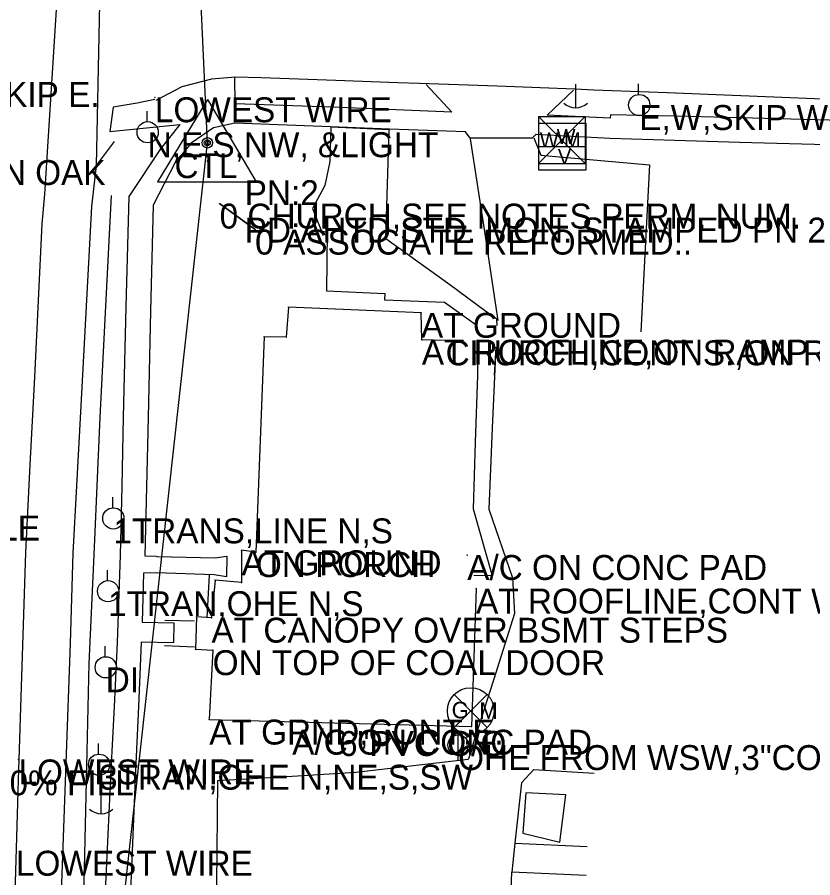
# Model space of a CAD drawing. Extents: x 997398 to 1003416, y 334596 to 337085.
# Drawn here: x 999233.9 to 999393.6, y 335108.7 to 335281.4 of the extents above; entities that cross this region are included whole.
import ezdxf

# ---------------------------------------------------------------- set-up
doc = ezdxf.new("R2010")
doc.units = 0
for name, color, linetype in [('Default', 7, 'Continuous'), ('S_BUILDING', 7, 'Continuous'), ('S_BUILDING_ANNOT', 7, 'Continuous'), ('S_CURB', 7, 'Continuous'), ('S_DITCHLINE', 7, 'Continuous'), ('S_EDGE_CONCRETE', 7, 'Continuous'), ('S_EDGE_PAVEMENT', 7, 'Continuous'), ('S_ELECTRIC_UTILITIES_ANNOT', 7, 'Continuous'), ('S_GAS_UTILITIES', 7, 'Continuous'), ('S_GRD_PT_SYM', 7, 'Continuous'), ('S_MISC_STRUCTURES_ANNOT', 7, 'Continuous'), ('S_MSC_PT_SYM', 7, 'Continuous'), ('S_PAVEMENT_CROWN', 7, 'Continuous'), ('S_PRIMARY_CTL', 7, 'Continuous'), ('S_PRIMARY_CTL_ANNOT', 7, 'Continuous'), ('S_SIDE_DRAIN_ANNOT', 7, 'Continuous'), ('S_SIDEWALK', 7, 'Continuous'), ('S_SIGN', 7, 'Continuous'), ('S_SIGN_ANNOT', 7, 'Continuous'), ('S_STR_PT_SYM', 7, 'Continuous'), ('S_TREE_ANNOT', 7, 'Continuous'), ('S_UTILITY_POLE', 7, 'Continuous'), ('S_UTILITY_POLE_ANNOT', 7, 'Continuous'), ('S_UTL_PT_SYM', 7, 'Continuous'), ('S_WALL', 7, 'Continuous'), ('S_WATER_UTILITIES', 7, 'Continuous')]:
    doc.layers.add(name, color=color, linetype=linetype)

msp = doc.modelspace()

# ---------------------------------------------------------------- linework, layer by layer
at = {"layer": 'Default'}
for p, q in [((999272.07, 335256.17), (999254.77, 335651.12)), ((999206.9, 334665.47), (999272.07, 335256.17))]:
    msp.add_line(p, q, dxfattribs=at)
at = {"layer": 'S_BUILDING'}
for p, q in [((999288.38, 335223.2), (999287.92, 335217.21)), ((999314.96, 335222.06), (999288.38, 335223.2)), ((999315.12, 335216.67), (999314.96, 335222.06)), ((999283.48, 335217.28), (999281.81, 335174.06)), ((999287.92, 335217.21), (999283.48, 335217.28)), ((999319.89, 335216.53), (999315.12, 335216.67)), ((999278.95, 335174.42), (999278.92, 335167.97)), ((999281.81, 335174.06), (999278.95, 335174.42)), ((999273.61, 335168.44), (999272.91, 335160.9)), ((999278.92, 335167.97), (999273.61, 335168.44)), ((999326.01, 335166.74), (999325.1, 335139.1)), ((999269.89, 335161.05), (999269.66, 335154.56)), ((999272.91, 335160.9), (999269.89, 335161.05)), ((999269.66, 335154.56), (999273.14, 335154.38)), ((999273.14, 335154.38), (999272.46, 335140.46)), ((999272.46, 335140.46), (999325.1, 335139.1))]:
    msp.add_line(p, q, dxfattribs=at)
at = {"layer": 'S_CURB'}
msp.add_lwpolyline([(999479.94, 335261.63), (999466.28, 335262.15), (999452.62, 335262.68), (999438.96, 335263.21), (999425.29, 335263.73), (999402.2, 335264.66), (999379.11, 335265.58), (999364.38, 335266.17), (999349.65, 335266.76), (999345.81, 335266.95), (999330.22, 335267.52), (999314.63, 335268.09), (999310.32, 335268.23), (999297.87, 335268.66), (999282.9, 335269.18), (999277.69, 335269.31), (999272.89, 335268.92), (999266.95, 335267.42), (999261.74, 335264.66)], dxfattribs=at)
at = {"layer": 'S_DITCHLINE'}
msp.add_lwpolyline([(999252.77, 335245.59), (999251.64, 335223.38), (999250.51, 335201.16), (999249.91, 335187.35), (999249.3, 335173.53), (999248.31, 335151.72), (999247.75, 335128.15), (999247.19, 335104.58), (999246.61, 335082.45), (999246.03, 335060.31), (999245.59, 335042.2), (999245.16, 335024.09)], dxfattribs=at)
at = {"layer": 'S_EDGE_CONCRETE'}
for points in [[(999330.26, 335219.49), (999330.2, 335220.82), (999327.72, 335222.53), (999320.73, 335227.65), (999307.89, 335236.94), (999308.58, 335258.8), (999296.86, 335259.33), (999296.65, 335252.42), (999295.64, 335247.63), (999293.16, 335243.01), (999294.95, 335238.44), (999296.11, 335238.34), (999295.96, 335226.51), (999307.69, 335225.96), (999307.63, 335224.64), (999319.66, 335224.2), (999326.05, 335219.68)], [(999272.05, 335160.9), (999272.52, 335169.46)], [(999343.99, 335125.34), (999335.96, 335125.79), (999335.36, 335117.66), (999342.79, 335115.87)], [(999342.79, 335115.87), (999343.99, 335125.34)]]:
    msp.add_lwpolyline(points, dxfattribs=at)
at = {"layer": 'S_EDGE_PAVEMENT'}
for points in [[(999250.53, 335290.61), (999250.16, 335271.12), (999249.78, 335251.63)], [(999253.37, 335256.43), (999249.78, 335251.63), (999248.81, 335243.39), (999247.69, 335222.16), (999246.57, 335200.94), (999245.83, 335187.38), (999245.09, 335173.83), (999244.51, 335155.82), (999243.66, 335131.7), (999242.8, 335107.59), (999242.11, 335084.06), (999241.43, 335060.53), (999241.09, 335044.29), (999240.74, 335028.05)], [(999330.41, 335220.52), (999327.66, 335238.75), (999324.91, 335256.98)], [(999337.56, 335257.14), (999339, 335253.7), (999360.79, 335251.76), (999359.92, 335235.01), (999359.06, 335218.27)], [(999325.44, 335135.07), (999324.44, 335132.45), (999301.88, 335129.85), (999288.01, 335129.01), (999274.14, 335128.17), (999273.91, 335107.32), (999273.67, 335086.47), (999273.64, 335073.11), (999273.61, 335059.74), (999273.58, 335046.38), (999273.55, 335033.02), (999273.11, 335010.86)], [(999335.09, 335127.78), (999337.61, 335130.43), (999349.71, 335129.72)], [(999335.09, 335127.78), (999333.79, 335115.69)], [(999331.73, 335071.66), (999332.45, 335090.76), (999333.17, 335109.85)]]:
    msp.add_lwpolyline(points, dxfattribs=at)
at = {"layer": 'S_GAS_UTILITIES'}
for p, q in [((999321.61, 335138.87), (999328.23, 335145.49)), ((999321.61, 335145.49), (999328.23, 335138.87))]:
    msp.add_line(p, q, dxfattribs=at)
msp.add_circle((999324.92, 335142.18), 4.68, dxfattribs=at)
at = {"layer": 'S_GRD_PT_SYM'}
for points in [[(999261.55, 335265.3), (999261.55, 335265.35), (999261.55, 335265.3), (999261.5, 335265.3), (999261.55, 335265.3), (999261.55, 335265.25), (999261.55, 335265.3), (999261.6, 335265.3)], [(999234.16, 335132.46), (999234.16, 335132.51), (999234.16, 335132.46), (999234.11, 335132.46), (999234.16, 335132.46), (999234.16, 335132.41), (999234.16, 335132.46), (999234.21, 335132.46)]]:
    msp.add_lwpolyline(points, dxfattribs=at)
at = {"layer": 'S_MSC_PT_SYM'}
for points in [[(999274.54, 335243.97), (999274.54, 335244.02), (999274.54, 335243.97), (999274.49, 335243.97), (999274.54, 335243.97), (999274.54, 335243.92), (999274.54, 335243.97), (999274.59, 335243.97)], [(999281.65, 335238.75), (999281.65, 335238.8), (999281.65, 335238.75), (999281.6, 335238.75), (999281.65, 335238.75), (999281.65, 335238.7), (999281.65, 335238.75), (999281.7, 335238.75)], [(999281.7, 335238.75), (999281.7, 335238.8), (999281.7, 335238.75), (999281.65, 335238.75), (999281.7, 335238.75), (999281.7, 335238.7), (999281.7, 335238.75), (999281.75, 335238.75)], [(999324.23, 335173.48), (999324.23, 335173.53), (999324.23, 335173.48), (999324.18, 335173.48), (999324.23, 335173.48), (999324.23, 335173.43), (999324.23, 335173.48), (999324.28, 335173.48)], [(999289.1, 335138.43), (999289.1, 335138.48), (999289.1, 335138.43), (999289.05, 335138.43), (999289.1, 335138.43), (999289.1, 335138.38), (999289.1, 335138.43), (999289.15, 335138.43)], [(999298.5, 335138.16), (999298.5, 335138.21), (999298.5, 335138.16), (999298.45, 335138.16), (999298.5, 335138.16), (999298.5, 335138.11), (999298.5, 335138.16), (999298.55, 335138.16)]]:
    msp.add_lwpolyline(points, dxfattribs=at)
at = {"layer": 'S_PAVEMENT_CROWN'}
msp.add_lwpolyline([(999231.13, 335025.58), (999231.54, 335039.84), (999231.96, 335054.1), (999232.37, 335068.37), (999232.78, 335082.63), (999233.49, 335105.48), (999234.2, 335128.32), (999234.91, 335151.16), (999235.62, 335174.01), (999236.52, 335191.6), (999237.42, 335209.19), (999238.19, 335224.55), (999238.95, 335239.91), (999239.44, 335245.85), (999240.93, 335269.15), (999242.42, 335292.45)], dxfattribs=at)
at = {"layer": 'S_PRIMARY_CTL'}
for p, q in [((999272.07, 335264.87), (999262.04, 335248.36)), ((999272.07, 335264.87), (999281.89, 335248.36)), ((999262.04, 335248.36), (999281.89, 335248.36))]:
    msp.add_line(p, q, dxfattribs=at)
for radius in [1.04, 0.609, 0.344]:
    msp.add_circle((999272.07, 335256.17), radius, dxfattribs=at)
at = {"layer": 'S_SIDEWALK'}
for points in [[(999316, 335267.89), (999321.17, 335262.33), (999296.97, 335263.29), (999277.65, 335264.02), (999277.6, 335269.25)], [(999479.54, 335257.17), (999465.91, 335257.86), (999452.28, 335258.55), (999438.64, 335259.23), (999425.01, 335259.92), (999401.97, 335260.55), (999378.93, 335261.19), (999365.95, 335261.49), (999352.97, 335261.78), (999352.89, 335261.13), (999340.29, 335261.71), (999345.53, 335266.72)], [(999261.5, 335264.87), (999257.97, 335264.12), (999253.16, 335263.29), (999252.5, 335258.44), (999266.54, 335259.86), (999262.66, 335254.95), (999256.3, 335245.42)], [(999479.13, 335252.32), (999465.35, 335252.98), (999451.57, 335253.65), (999437.79, 335254.31), (999424.01, 335254.97), (999401.43, 335255.6), (999378.85, 335256.22), (999365.86, 335256.64), (999352.87, 335257.07), (999338.02, 335257.84), (999337.27, 335257.09), (999324.82, 335257.13), (999323.89, 335258.38), (999308.61, 335258.94), (999296.79, 335259.38), (999277.61, 335260.14), (999273.31, 335259.2), (999268.8, 335256.09), (999265.61, 335252.19), (999261.19, 335243.68)], [(999256.3, 335245.42), (999255.74, 335223.28), (999255.18, 335201.13)], [(999261.19, 335243.68), (999260.69, 335222.38), (999260.19, 335201.09)], [(999326.27, 335215.31), (999326.26, 335209.47)], [(999329.98, 335215.17), (999329.26, 335198.93), (999328.54, 335182.7)], [(999329.98, 335215.17), (999329.6, 335209.59)], [(999326.26, 335209.47), (999325.85, 335196.11), (999325.43, 335182.76)], [(999255.18, 335201.13), (999254.88, 335187.29), (999254.58, 335173.44), (999253.96, 335155.96), (999253.34, 335143.12), (999252.73, 335130.28), (999252.11, 335117.44), (999251.5, 335104.6), (999250.76, 335082.39), (999250.02, 335060.17), (999249.36, 335042.19), (999248.7, 335024.21)], [(999260.19, 335201.09), (999259.85, 335187.19), (999259.51, 335173.29), (999261.77, 335173.24), (999261.91, 335173.2), (999273.63, 335172.94), (999275.99, 335173.22), (999275.89, 335169.08), (999273.44, 335169.51), (999261.84, 335169.89), (999259.26, 335169.84), (999258.98, 335159.99), (999265.32, 335159.89), (999265.3, 335155.88), (999258.79, 335155.99), (999258.23, 335143.09), (999257.67, 335130.2), (999257.11, 335117.3), (999256.56, 335104.4), (999255.74, 335082.14), (999254.93, 335059.88), (999254.31, 335042.1), (999253.7, 335024.32)], [(999328.54, 335182.7), (999333.29, 335168.87), (999333.74, 335161.76), (999329.47, 335148.4), (999325.21, 335135.04)], [(999325.43, 335182.76), (999329.21, 335169.3), (999325.52, 335169.38)], [(999333.79, 335115.69), (999333.17, 335109.85)], [(999333.79, 335115.69), (999348.33, 335115.02)], [(999348.1, 335109.19), (999333.17, 335109.85)]]:
    msp.add_lwpolyline(points, dxfattribs=at)
at = {"layer": 'S_SIGN'}
for p, q in [((999281.7, 335238.75), (999274.54, 335243.97)), ((999274.54, 335243.97), (999281.65, 335238.75))]:
    msp.add_line(p, q, dxfattribs=at)
at = {"layer": 'S_STR_PT_SYM'}
for points in [[(999288.38, 335223.2), (999288.38, 335223.25), (999288.38, 335223.2), (999288.33, 335223.2), (999288.38, 335223.2), (999288.38, 335223.15), (999288.38, 335223.2), (999288.43, 335223.2)], [(999314.96, 335222.06), (999314.96, 335222.11), (999314.96, 335222.06), (999314.91, 335222.06), (999314.96, 335222.06), (999314.96, 335222.01), (999314.96, 335222.06), (999315.01, 335222.06)], [(999283.48, 335217.28), (999283.48, 335217.33), (999283.48, 335217.28), (999283.43, 335217.28), (999283.48, 335217.28), (999283.48, 335217.23), (999283.48, 335217.28), (999283.53, 335217.28)], [(999287.92, 335217.21), (999287.92, 335217.26), (999287.92, 335217.21), (999287.87, 335217.21), (999287.92, 335217.21), (999287.92, 335217.16), (999287.92, 335217.21), (999287.97, 335217.21)], [(999315.12, 335216.67), (999315.12, 335216.72), (999315.12, 335216.67), (999315.07, 335216.67), (999315.12, 335216.67), (999315.12, 335216.62), (999315.12, 335216.67), (999315.17, 335216.67)], [(999319.89, 335216.53), (999319.89, 335216.58), (999319.89, 335216.53), (999319.84, 335216.53), (999319.89, 335216.53), (999319.89, 335216.48), (999319.89, 335216.53), (999319.94, 335216.53)], [(999278.95, 335174.42), (999278.95, 335174.47), (999278.95, 335174.42), (999278.9, 335174.42), (999278.95, 335174.42), (999278.95, 335174.37), (999278.95, 335174.42), (999279, 335174.42)], [(999281.81, 335174.06), (999281.81, 335174.11), (999281.81, 335174.06), (999281.76, 335174.06), (999281.81, 335174.06), (999281.81, 335174.01), (999281.81, 335174.06), (999281.86, 335174.06)], [(999273.61, 335168.44), (999273.61, 335168.49), (999273.61, 335168.44), (999273.56, 335168.44), (999273.61, 335168.44), (999273.61, 335168.39), (999273.61, 335168.44), (999273.66, 335168.44)], [(999278.92, 335167.97), (999278.92, 335168.02), (999278.92, 335167.97), (999278.87, 335167.97), (999278.92, 335167.97), (999278.92, 335167.92), (999278.92, 335167.97), (999278.97, 335167.97)], [(999326.01, 335166.74), (999326.01, 335166.79), (999326.01, 335166.74), (999325.96, 335166.74), (999326.01, 335166.74), (999326.01, 335166.69), (999326.01, 335166.74), (999326.06, 335166.74)], [(999269.89, 335161.05), (999269.89, 335161.1), (999269.89, 335161.05), (999269.84, 335161.05), (999269.89, 335161.05), (999269.89, 335161), (999269.89, 335161.05), (999269.94, 335161.05)], [(999272.91, 335160.9), (999272.91, 335160.95), (999272.91, 335160.9), (999272.86, 335160.9), (999272.91, 335160.9), (999272.91, 335160.85), (999272.91, 335160.9), (999272.96, 335160.9)], [(999269.66, 335154.56), (999269.66, 335154.61), (999269.66, 335154.56), (999269.6, 335154.56), (999269.66, 335154.56), (999269.66, 335154.51), (999269.66, 335154.56), (999269.71, 335154.56)], [(999273.14, 335154.38), (999273.14, 335154.43), (999273.14, 335154.38), (999273.09, 335154.38), (999273.14, 335154.38), (999273.14, 335154.33), (999273.14, 335154.38), (999273.19, 335154.38)], [(999272.46, 335140.46), (999272.46, 335140.51), (999272.46, 335140.46), (999272.41, 335140.46), (999272.46, 335140.46), (999272.46, 335140.41), (999272.46, 335140.46), (999272.51, 335140.46)], [(999325.1, 335139.1), (999325.1, 335139.15), (999325.1, 335139.1), (999325.05, 335139.1), (999325.1, 335139.1), (999325.1, 335139.05), (999325.1, 335139.1), (999325.15, 335139.1)]]:
    msp.add_lwpolyline(points, dxfattribs=at)
at = {"layer": 'S_UTILITY_POLE'}
for p, q in [((999345.93, 335267.92), (999345.93, 335263.19)), ((999358.62, 335265.88), (999358.62, 335267.99)), ((999259.97, 335260.43), (999259.97, 335262.54)), ((999253.09, 335182.96), (999253.09, 335185.07)), ((999252.03, 335168.36), (999252.03, 335170.47)), ((999251.55, 335153.09), (999251.55, 335155.19)), ((999322.41, 335132.41), (999322.41, 335138.2)), ((999250.22, 335133.54), (999250.22, 335135.65)), ((999250.71, 335126.29), (999250.71, 335121.56))]:
    msp.add_line(p, q, dxfattribs=at)
for centre, radius in [((999358.75, 335263.74), 2.13), ((999260.09, 335258.29), 2.13), ((999253.21, 335180.82), 2.13), ((999252.15, 335166.22), 2.13), ((999251.68, 335150.94), 2.13), ((999322.41, 335135.34), 2.05), ((999250.34, 335131.4), 2.13)]:
    msp.add_circle(centre, radius, dxfattribs=at)
for centre in [(999345.99, 335266.61), (999250.77, 335124.99)]:
    msp.add_arc(centre, 3.41, 226.3972, 313.6028, dxfattribs=at)
at = {"layer": 'S_UTL_PT_SYM'}
for points in [[(999261.55, 335265.3), (999261.55, 335265.35), (999261.55, 335265.3), (999261.5, 335265.3), (999261.55, 335265.3), (999261.55, 335265.25), (999261.55, 335265.3), (999261.6, 335265.3)], [(999234.16, 335132.46), (999234.16, 335132.51), (999234.16, 335132.46), (999234.11, 335132.46), (999234.16, 335132.46), (999234.16, 335132.41), (999234.16, 335132.46), (999234.21, 335132.46)]]:
    msp.add_lwpolyline(points, dxfattribs=at)
at = {"layer": 'S_WALL'}
for points in [[(999263.51, 335160.38), (999269.51, 335160.27)], [(999263.45, 335155.34), (999269.47, 335155.07)]]:
    msp.add_lwpolyline(points, dxfattribs=at)
at = {"layer": 'S_WATER_UTILITIES'}
for p, q in [((999338.56, 335261.48), (999347.9, 335261.48)), ((999338.56, 335261.48), (999338.56, 335251.99)), ((999338.56, 335261.48), (999347.9, 335251.99)), ((999347.9, 335261.48), (999338.56, 335251.99)), ((999347.9, 335261.48), (999347.9, 335251.99)), ((999338.63, 335260.12), (999348.05, 335260.12)), ((999338.63, 335250.71), (999338.63, 335260.12)), ((999348.05, 335260.12), (999348.05, 335250.71)), ((999338.63, 335255.43), (999348.05, 335255.43)), ((999338.56, 335251.99), (999347.9, 335251.99)), ((999348.05, 335250.71), (999338.63, 335250.71))]:
    msp.add_line(p, q, dxfattribs=at)

# ---------------------------------------------------------------- texts
at = {"layer": 'S_BUILDING_ANNOT'}
for s, p in [('AT GROUND', (999314.96, 335217.06)), ('AT ROOFLINE,ON RAMP', (999315.12, 335211.67)), ('CHURCH,CONT.S.,ON RAMP', (999319.89, 335211.53)), ('AT GROUND', (999278.95, 335169.42)), ('ON PORCH', (999281.81, 335169.06)), ('AT ROOFLINE,CONT W ON STEPS', (999326.01, 335161.74)), ('AT CANOPY OVER BSMT STEPS', (999272.91, 335155.9)), ('ON TOP OF COAL DOOR', (999273.14, 335149.38)), ('AT GRND,CONT.E.', (999272.46, 335135.46))]:
    msp.add_text(s, height=5, dxfattribs=at).set_placement(p)
at = {"layer": 'S_ELECTRIC_UTILITIES_ANNOT'}
for p in [(999261.55, 335260.3), (999234.16, 335127.46), (999233.66, 335109.15)]:
    msp.add_text('LOWEST WIRE', height=5, dxfattribs=at).set_placement(p)
at = {"layer": 'S_GAS_UTILITIES'}
for s, p in [('G', (999321.1, 335140.72)), ('M', (999326.66, 335140.61))]:
    msp.add_text(s, height=3.3, rotation=360, dxfattribs=at).set_placement(p)
at = {"layer": 'S_MISC_STRUCTURES_ANNOT'}
for s, p in [('A/C ON CONC PAD', (999324.23, 335168.48)), ('A/C ON CONC PAD', (999289.1, 335133.43)), ('6"PVC C/O', (999298.5, 335133.16))]:
    msp.add_text(s, height=5, dxfattribs=at).set_placement(p)
at = {"layer": 'S_PRIMARY_CTL'}
msp.add_text('CTL', height=5, rotation=360, dxfattribs=at).set_placement((999265.48, 335249.09))
at = {"layer": 'S_PRIMARY_CTL_ANNOT'}
for s, p in [('PN:2', (999279.57, 335243.67)), ('PD:AHTD STD. MON. STAMPED PN 2', (999279.57, 335236.17))]:
    msp.add_text(s, height=5, dxfattribs=at).set_placement(p)
at = {"layer": 'S_SIDE_DRAIN_ANNOT'}
msp.add_text('CN:80% FILL', height=5, dxfattribs=at).set_placement((999217.15, 335125.27))
at = {"layer": 'S_SIGN_ANNOT'}
for s, p in [('0 CHURCH,SEE NOTES PERM. NUM.', (999274.54, 335238.97)), ('0', (999281.65, 335233.75)), ('0 ASSOCIATE REFORMED..', (999281.7, 335233.75))]:
    msp.add_text(s, height=5, dxfattribs=at).set_placement(p)
at = {"layer": 'S_TREE_ANNOT'}
for s, p in [('36PIN OAK', (999217.08, 335247.71)), ('48MAPLE', (999208.37, 335176.38))]:
    msp.add_text(s, height=5, dxfattribs=at).set_placement(p)
at = {"layer": 'S_UTILITY_POLE_ANNOT'}
for s, p in [('N,SKIP E.', (999220.35, 335263.37)), ('E,W,SKIP W', (999358.75, 335258.74)), ('N,E,S,NW, &LIGHT', (999260.09, 335253.29)), ('1TRANS,LINE N,S', (999253.21, 335175.82)), ('1TRAN,OHE N,S', (999252.15, 335161.22)), ('DI', (999251.68, 335145.94)), ('OHE FROM WSW,3"CONDUIT.. ..TO E', (999322.41, 335130.34)), ('3TRAN,OHE N,NE,S,SW', (999250.34, 335126.4))]:
    msp.add_text(s, height=5, dxfattribs=at).set_placement(p)
at = {"layer": 'S_WATER_UTILITIES'}
for s, p in [('W M', (999338.77, 335255.25)), ('W', (999342.18, 335255.96)), ('V', (999342.42, 335251.9))]:
    msp.add_text(s, height=3, rotation=360, dxfattribs=at).set_placement(p)

doc.saveas('drawing.dxf')
